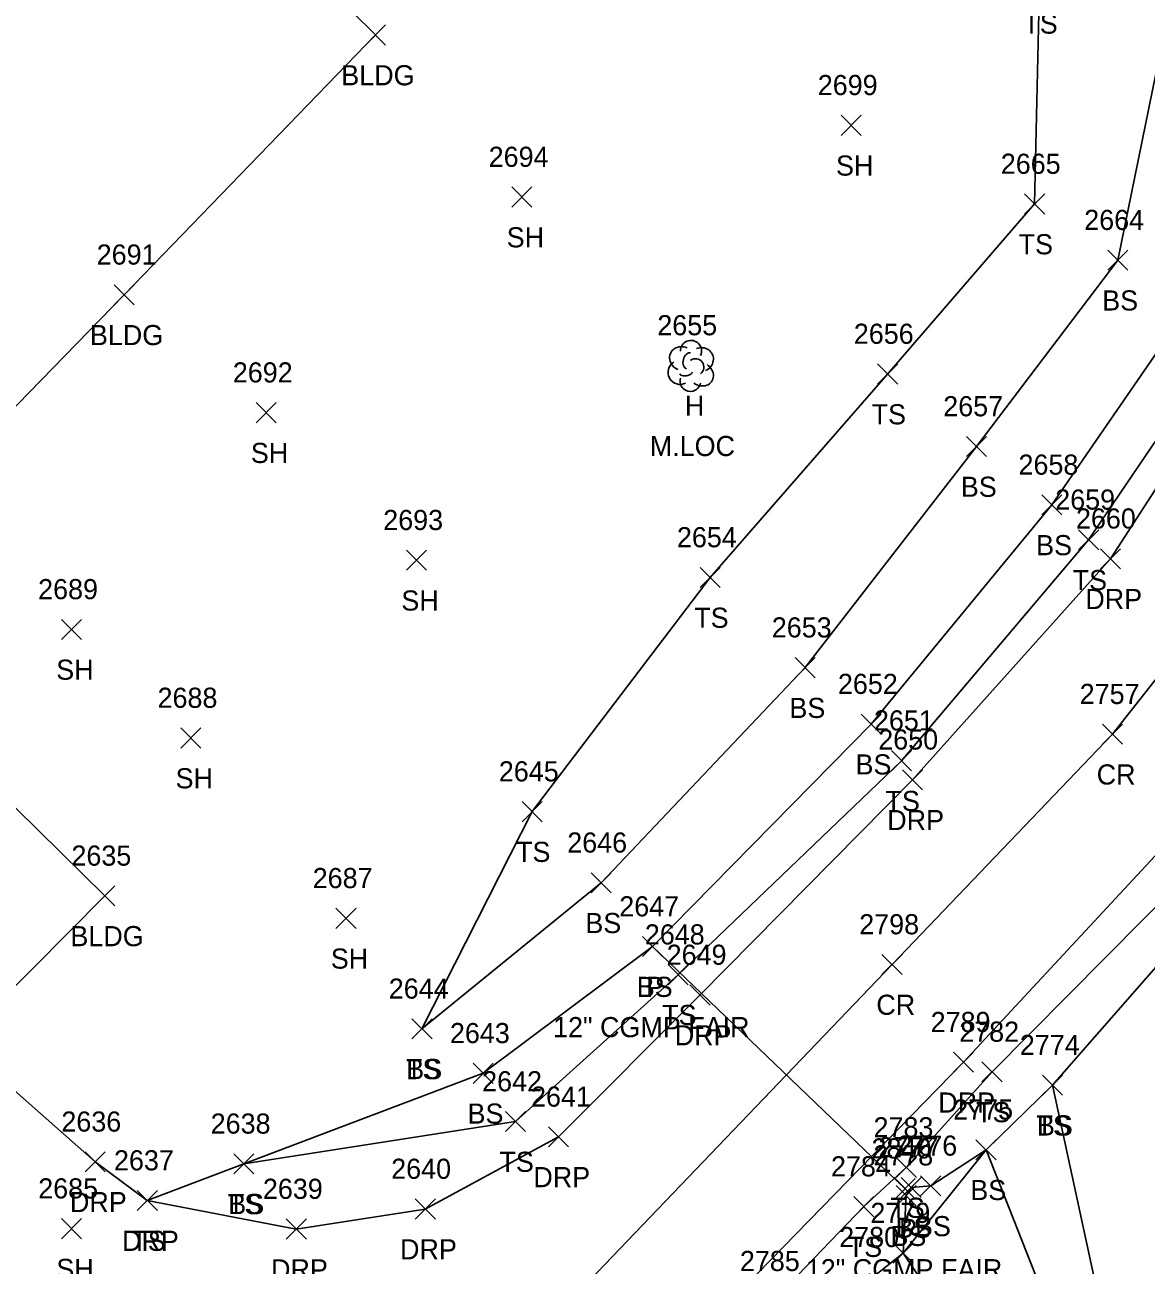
# Model space of a CAD drawing. Extents: x 1472233 to 1475777, y 540726 to 543442.
# Drawn here: x 1474005.9 to 1474117.3, y 542676.8 to 542800 of the extents above; entities that cross this region are included whole.
import ezdxf

# ---------------------------------------------------------------- set-up
doc = ezdxf.new("R2010")
doc.units = 0
for name, color, linetype in [('D_A', 7, 'Continuous'), ('D_C', 7, 'Continuous'), ('D_I', 7, 'Continuous'), ('D_TIC', 7, 'Continuous'), ('DCP', 7, 'Continuous'), ('L_A', 7, 'Continuous'), ('L_C', 7, 'Continuous'), ('L_I', 7, 'Continuous'), ('L_TIC', 7, 'Continuous'), ('LBC', 7, 'Continuous'), ('LELB', 7, 'Continuous'), ('LSOGP', 7, 'Continuous'), ('LTD', 7, 'Continuous'), ('P_A', 7, 'Continuous'), ('P_I', 7, 'Continuous'), ('P_TIC', 7, 'Continuous'), ('PRC', 7, 'Continuous'), ('R_A', 7, 'Continuous'), ('R_I', 7, 'Continuous'), ('R_TIC', 7, 'Continuous'), ('RDP', 7, 'Continuous')]:
    doc.layers.add(name, color=color, linetype=linetype)

msp = doc.modelspace()

# ---------------------------------------------------------------- linework, layer by layer
at = {"layer": 'D_TIC'}
for points in [[(1474067.24, 542707.41), (1474069.24, 542709.41)], [(1474069.24, 542707.41), (1474067.24, 542709.41)], [(1474092.36, 542683.36), (1474094.36, 542685.36)], [(1474094.36, 542683.36), (1474092.36, 542685.36)]]:
    msp.add_lwpolyline(points, dxfattribs=at)
at = {"layer": 'DCP'}
msp.add_lwpolyline([(1474068.24, 542708.41), (1474093.36, 542684.36)], dxfattribs=at)
at = {"layer": 'L_TIC'}
for points in [[(1474039.72, 542797.97), (1474041.72, 542799.97)], [(1474041.72, 542797.97), (1474039.72, 542799.97)], [(1474086.99, 542789), (1474088.99, 542791)], [(1474088.99, 542789), (1474086.99, 542791)], [(1474054.26, 542781.87), (1474056.26, 542783.87)], [(1474056.26, 542781.87), (1474054.26, 542783.87)], [(1474105.22, 542781.18), (1474107.22, 542783.18)], [(1474107.22, 542781.18), (1474105.22, 542783.18)], [(1474113.5, 542775.6), (1474115.5, 542777.6)], [(1474115.5, 542775.6), (1474113.5, 542777.6)], [(1474014.74, 542772.16), (1474016.74, 542774.16)], [(1474016.74, 542772.16), (1474014.74, 542774.16)], [(1474090.61, 542764.29), (1474092.61, 542766.29)], [(1474092.61, 542764.29), (1474090.61, 542766.29)], [(1474028.84, 542760.45), (1474030.84, 542762.45)], [(1474030.84, 542760.45), (1474028.84, 542762.45)], [(1474099.45, 542757.09), (1474101.45, 542759.09)], [(1474101.45, 542757.09), (1474099.45, 542759.09)], [(1474106.93, 542751.29), (1474108.93, 542753.29)], [(1474108.93, 542751.29), (1474106.93, 542753.29)], [(1474110.59, 542747.82), (1474112.59, 542749.82)], [(1474112.59, 542747.82), (1474110.59, 542749.82)], [(1474043.79, 542745.79), (1474045.79, 542747.79)], [(1474045.79, 542745.79), (1474043.79, 542747.79)], [(1474072.98, 542744.08), (1474074.98, 542746.08)], [(1474074.98, 542744.08), (1474072.98, 542746.08)], [(1474009.49, 542738.92), (1474011.49, 542740.92)], [(1474011.49, 542738.92), (1474009.49, 542740.92)], [(1474082.41, 542735.12), (1474084.41, 542737.12)], [(1474084.41, 542735.12), (1474082.41, 542737.12)], [(1474088.98, 542729.51), (1474090.98, 542731.51)], [(1474090.98, 542729.51), (1474088.98, 542731.51)], [(1474021.35, 542728.13), (1474023.35, 542730.13)], [(1474023.35, 542728.13), (1474021.35, 542730.13)], [(1474091.99, 542725.88), (1474093.99, 542727.88)], [(1474093.99, 542725.88), (1474091.99, 542727.88)], [(1474055.28, 542720.82), (1474057.28, 542722.82)], [(1474057.28, 542720.82), (1474055.28, 542722.82)], [(1474062.13, 542713.75), (1474064.13, 542715.75)], [(1474064.13, 542713.75), (1474062.13, 542715.75)], [(1474012.8, 542712.45), (1474014.8, 542714.45)], [(1474014.8, 542712.45), (1474012.8, 542714.45)], [(1474036.78, 542710.22), (1474038.78, 542712.22)], [(1474038.78, 542710.22), (1474036.78, 542712.22)], [(1474067.24, 542707.41), (1474069.24, 542709.41)], [(1474069.24, 542707.41), (1474067.24, 542709.41)], [(1474069.79, 542704.62), (1474071.79, 542706.62)], [(1474071.79, 542704.62), (1474069.79, 542706.62)], [(1474044.33, 542699.24), (1474046.33, 542701.24)], [(1474046.33, 542699.24), (1474044.33, 542701.24)], [(1474044.33, 542699.24), (1474046.33, 542701.24)], [(1474046.33, 542699.24), (1474044.33, 542701.24)], [(1474050.42, 542694.82), (1474052.42, 542696.82)], [(1474052.42, 542694.82), (1474050.42, 542696.82)], [(1474100.99, 542694.96), (1474102.99, 542696.96)], [(1474102.99, 542694.96), (1474100.99, 542696.96)], [(1474107, 542693.64), (1474109, 542695.64)], [(1474109, 542693.64), (1474107, 542695.64)], [(1474107, 542693.64), (1474109, 542695.64)], [(1474109, 542693.64), (1474107, 542695.64)], [(1474053.62, 542690.03), (1474055.62, 542692.03)], [(1474055.62, 542690.03), (1474053.62, 542692.03)], [(1474100.39, 542687.23), (1474102.39, 542689.23)], [(1474102.39, 542687.23), (1474100.39, 542689.23)], [(1474100.39, 542687.23), (1474102.39, 542689.23)], [(1474102.39, 542687.23), (1474100.39, 542689.23)], [(1474026.63, 542685.83), (1474028.63, 542687.83)], [(1474028.63, 542685.83), (1474026.63, 542687.83)], [(1474026.63, 542685.83), (1474028.63, 542687.83)], [(1474028.63, 542685.83), (1474026.63, 542687.83)], [(1474092.47, 542685.46), (1474094.47, 542687.46)], [(1474094.47, 542685.46), (1474092.47, 542687.46)], [(1474092.95, 542683.48), (1474094.95, 542685.48)], [(1474094.95, 542683.48), (1474092.95, 542685.48)], [(1474094.89, 542683.64), (1474096.89, 542685.64)], [(1474096.89, 542683.64), (1474094.89, 542685.64)], [(1474017.03, 542682.18), (1474019.03, 542684.18)], [(1474019.03, 542682.18), (1474017.03, 542684.18)], [(1474092.45, 542682.67), (1474094.45, 542684.67)], [(1474094.45, 542682.67), (1474092.45, 542684.67)], [(1474088.24, 542681.58), (1474090.24, 542683.58)], [(1474090.24, 542681.58), (1474088.24, 542683.58)], [(1474009.5, 542679.39), (1474011.5, 542681.39)], [(1474011.5, 542679.39), (1474009.5, 542681.39)], [(1474092.16, 542676.96), (1474094.16, 542678.96)], [(1474094.16, 542676.96), (1474092.16, 542678.96)], [(1474092.16, 542676.96), (1474094.16, 542678.96)], [(1474094.16, 542676.96), (1474092.16, 542678.96)]]:
    msp.add_lwpolyline(points, dxfattribs=at)
at = {"layer": 'LBC'}
msp.add_lwpolyline([(1473611.81, 542877.43), (1473647.84, 542842.15), (1473684.15, 542806.79), (1473712.79, 542779.19), (1473741.79, 542750.87), (1473773.96, 542719.66), (1473804, 542690.56), (1473836.45, 542659.06), (1473871.86, 542624.85), (1473901.94, 542656.08), (1473913.55, 542668.06), (1473934.21, 542647.92), (1473934.79, 542648.35), (1473977.15, 542693.11), (1473991.17, 542706.54), (1473991.24, 542706.56), (1473999.37, 542698.9), (1474013.8, 542713.45), (1473985.08, 542741.69), (1474015.74, 542773.16), (1474040.72, 542798.97), (1474028.75, 542810.8)], dxfattribs=at)
at = {"layer": 'LELB'}
for points in [[(1474018.03, 542683.18), (1474027.63, 542686.83), (1474054.62, 542691.03), (1474070.79, 542705.62), (1474092.99, 542726.88), (1474111.59, 542748.82), (1474125.85, 542769.85), (1474132.06, 542791.22), (1474131.8, 542814.84), (1474116.48, 542854.31), (1474111.7, 542860.51)], [(1474027.63, 542686.83), (1474051.42, 542695.82), (1474068.24, 542708.41), (1474089.98, 542730.51), (1474107.93, 542752.29), (1474121.88, 542772.53), (1474127.08, 542791.58), (1474127.12, 542813.94), (1474113.55, 542845.74), (1474102.69, 542855.23)], [(1474045.33, 542700.24), (1474063.13, 542714.75), (1474083.41, 542736.12), (1474100.45, 542758.09), (1474114.5, 542776.6), (1474118.95, 542798.51), (1474116.01, 542812.59), (1474102.38, 542835.59), (1474091.33, 542848.77)], [(1474045.33, 542700.24), (1474056.28, 542721.82), (1474073.98, 542745.08), (1474091.61, 542765.29), (1474106.22, 542782.18), (1474106.69, 542804.1), (1474107.48, 542810.21), (1474096.9, 542832.11), (1474081.02, 542842.42)], [(1474161.33, 542816.84), (1474161.97, 542792.29), (1474154.87, 542762.03), (1474144.32, 542744.44), (1474124.61, 542718.74), (1474101.99, 542695.96), (1474093.47, 542686.46), (1474089.24, 542682.58), (1474080.19, 542673.18), (1474075.15, 542661.11), (1474077.15, 542641.54), (1474095.47, 542632.72), (1474116.89, 542615.57), (1474111.23, 542585.69), (1474090.52, 542556.35), (1474073.67, 542551.32), (1474038.07, 542519.87), (1474011.53, 542544.93), (1473997.92, 542550.92)], [(1474168.42, 542758.16), (1474161.08, 542732.65), (1474152.4, 542685.62), (1474143.99, 542650.7), (1474139.21, 542638.25), (1474125.13, 542652.19), (1474113.17, 542670.76), (1474108, 542694.64)], [(1474147.6, 542740.17), (1474126.67, 542715.96), (1474108, 542694.64), (1474101.39, 542688.23), (1474093.16, 542677.96), (1474090.14, 542675.56), (1474083.3, 542668.09), (1474080.25, 542657.73), (1474086.54, 542649.05), (1474102.87, 542638.26), (1474116.97, 542621), (1474129.54, 542610.53)], [(1474165.95, 542731.94), (1474157.14, 542683.61), (1474148.57, 542649.89), (1474143.29, 542635.5), (1474139.19, 542631.93), (1474131.36, 542636.12), (1474120.53, 542648.69), (1474108.56, 542670.06), (1474101.39, 542688.23), (1474095.89, 542684.64), (1474093.95, 542684.48), (1474093.45, 542683.67), (1474093.16, 542677.96), (1474112.56, 542649.15), (1474130.63, 542628.83), (1474135.77, 542616.46), (1474134.45, 542606.68), (1474129.24, 542593.89), (1474099.76, 542548.63), (1474087.76, 542535.06), (1474054.57, 542501.68), (1474028.74, 542469.85), (1474011.69, 542457.24), (1473991.56, 542429.6)]]:
    msp.add_lwpolyline(points, dxfattribs=at)
at = {"layer": 'LSOGP'}
msp.add_lwpolyline([(1473684.15, 542806.79), (1473712.79, 542779.19), (1473741.79, 542750.87), (1473773.96, 542719.66), (1473804, 542690.56), (1473836.45, 542659.06), (1473871.86, 542624.85), (1473901.94, 542656.08), (1473913.55, 542668.06), (1473934.21, 542647.92), (1473934.79, 542648.35), (1473977.15, 542693.11), (1473991.17, 542706.54), (1473991.24, 542706.56), (1473999.37, 542698.9), (1474013.8, 542713.45), (1473985.08, 542741.69), (1474015.74, 542773.16), (1474040.72, 542798.97), (1474028.75, 542810.8)], dxfattribs=at)
at = {"layer": 'LTD'}
msp.add_line((1474072.02, 542766.14), (1474072.02, 542766.14), dxfattribs=at)
msp.add_line((1474072.02, 542766.14), (1474072.02, 542766.14), dxfattribs=at)
msp.add_arc((1474072.07, 542767.58), 1.05, 335.5272, 180.9563, dxfattribs=at)
for centre, major_axis, ratio, start_param, end_param in [((1474071.23, 542766.81), (1.21, -0.51), 0.895232, 1.570796, 4.712389), ((1474071.82, 542766.6), (-0.208, -0.792), 0.645439, 3.141593, 6.283185), ((1474073.07, 542766.73), (-1.14, -0.48), 0.949671, 1.570796, 4.712389), ((1474070.94, 542765.43), (0.58, -1.04), 0.959034, 3.141593, 6.283185), ((1474072.52, 542765.98), (-0.5, 0.667), 0.989748, 3.141593, 6.283185), ((1474073.02, 542765.31), (-1.09, 0.79), 0.841452, 1.570796, 4.712389), ((1474071.57, 542765.39), (-0.625, -0.083), 0.423636, 0, 3.141593), ((1474072.02, 542764.64), (0.26, 1.06), 0.942809, 1.570796, 4.712389)]:
    msp.add_ellipse(centre, major_axis=major_axis, ratio=ratio, start_param=start_param, end_param=end_param, dxfattribs=at)
at = {"layer": 'P_TIC'}
for points in [[(1474112.96, 542728.51), (1474114.96, 542730.51)], [(1474114.96, 542728.51), (1474112.96, 542730.51)], [(1474091.05, 542705.63), (1474093.05, 542707.63)], [(1474093.05, 542705.63), (1474091.05, 542707.63)]]:
    msp.add_lwpolyline(points, dxfattribs=at)
at = {"layer": 'PRC'}
msp.add_lwpolyline([(1474124.73, 542867.45), (1474138.24, 542842.57), (1474146.26, 542814.27), (1474147.99, 542793.2), (1474140.2, 542767.69), (1474131.39, 542751.59), (1474113.96, 542729.51), (1474092.05, 542706.63), (1474043.97, 542656.44), (1473995.22, 542610.58), (1473969.45, 542582.1), (1473923.18, 542533.15), (1473898.02, 542503.68), (1473870.62, 542473.58), (1473851.91, 542452.04)], dxfattribs=at)
at = {"layer": 'R_TIC'}
for points in [[(1474112.77, 542745.94), (1474114.77, 542747.94)], [(1474114.77, 542745.94), (1474112.77, 542747.94)], [(1474093.08, 542723.98), (1474095.08, 542725.98)], [(1474095.08, 542723.98), (1474093.08, 542725.98)], [(1474071.96, 542702.6), (1474073.96, 542704.6)], [(1474073.96, 542702.6), (1474071.96, 542704.6)], [(1474098.16, 542695.92), (1474100.16, 542697.92)], [(1474100.16, 542695.92), (1474098.16, 542697.92)], [(1474057.91, 542688.51), (1474059.91, 542690.51)], [(1474059.91, 542688.51), (1474057.91, 542690.51)], [(1474011.85, 542686.03), (1474013.85, 542688.03)], [(1474013.85, 542686.03), (1474011.85, 542688.03)], [(1474017.03, 542682.18), (1474019.03, 542684.18)], [(1474019.03, 542682.18), (1474017.03, 542684.18)], [(1474044.66, 542681.34), (1474046.66, 542683.34)], [(1474046.66, 542681.34), (1474044.66, 542683.34)], [(1474031.84, 542679.35), (1474033.84, 542681.35)], [(1474033.84, 542679.35), (1474031.84, 542681.35)]]:
    msp.add_lwpolyline(points, dxfattribs=at)
at = {"layer": 'RDP'}
for points in [[(1473999.37, 542698.9), (1474012.85, 542687.03), (1474018.03, 542683.18), (1474032.84, 542680.35), (1474045.66, 542682.34), (1474058.91, 542689.51), (1474072.96, 542703.6), (1474094.08, 542724.98), (1474113.77, 542746.94), (1474127.81, 542768.61), (1474135.07, 542788.71), (1474134.76, 542814.36), (1474118.74, 542856.08), (1474114.45, 542861.9)], [(1474156.9, 542816.07), (1474158.25, 542792.55), (1474149.71, 542763.53), (1474141.06, 542745.97), (1474122.05, 542721.57), (1474099.16, 542696.92), (1474072.3, 542669.38), (1474064.97, 542659.15), (1474064.16, 542645.99), (1474070.96, 542633.45), (1474104.89, 542594.5), (1474067.57, 542556.96), (1474038.11, 542526.02), (1474001.11, 542557.22), (1473988.17, 542557.88), (1473978.19, 542554.56), (1473968.9, 542548.06), (1473950.18, 542529.64), (1473913.19, 542491.65), (1473890.53, 542466.06), (1473881.45, 542451.89), (1473878.79, 542441.67), (1473879.57, 542429.36), (1473882.06, 542422.12)]]:
    msp.add_lwpolyline(points, dxfattribs=at)

# ---------------------------------------------------------------- texts
at = {"layer": 'D_A'}
for p in [(1474067.62, 542703.41), (1474092.74, 542679.36)]:
    msp.add_text('P', height=2, dxfattribs=at).set_placement(p)
at = {"layer": 'D_C'}
for p in [(1474058.36, 542699.41), (1474083.48, 542675.36)]:
    msp.add_text('12" CGMP FAIR', height=2, dxfattribs=at).set_placement(p)
at = {"layer": 'D_I'}
for s, p in [('2647', (1474064.94, 542711.41)), ('2840', (1474090.01, 542687.36))]:
    msp.add_text(s, height=2, dxfattribs=at).set_placement(p)
at = {"layer": 'L_A'}
for s, p in [('TS', (1474105.1, 542799.1)), ('BLDG', (1474037.31, 542793.97)), ('SH', (1474086.48, 542785)), ('SH', (1474053.75, 542777.87)), ('TS', (1474104.63, 542777.18)), ('BS', (1474112.94, 542771.6)), ('BLDG', (1474012.33, 542768.16)), ('H', (1474071.46, 542761.14)), ('TS', (1474090.02, 542760.29)), ('SH', (1474028.32, 542756.45)), ('BS', (1474098.89, 542753.09)), ('BS', (1474106.37, 542747.29)), ('TS', (1474110, 542743.82)), ('SH', (1474043.28, 542741.79)), ('TS', (1474072.39, 542740.08)), ('SH', (1474008.98, 542734.92)), ('BS', (1474081.85, 542731.12)), ('BS', (1474088.42, 542725.51)), ('SH', (1474020.84, 542724.13)), ('TS', (1474091.4, 542721.88)), ('TS', (1474054.68, 542716.82)), ('BS', (1474061.57, 542709.75)), ('BLDG', (1474010.39, 542708.45)), ('SH', (1474036.27, 542706.22)), ('BS', (1474066.68, 542703.41)), ('TS', (1474069.2, 542700.62)), ('TS', (1474043.74, 542695.24)), ('BS', (1474043.77, 542695.24)), ('BS', (1474049.86, 542690.82)), ('TS', (1474100.4, 542690.96)), ('TS', (1474106.41, 542689.64)), ('BS', (1474106.45, 542689.64)), ('TS', (1474053.03, 542686.03)), ('BS', (1474099.83, 542683.23)), ('BS', (1474099.83, 542683.23)), ('TS', (1474026.04, 542681.83)), ('BS', (1474026.08, 542681.83)), ('TS', (1474091.88, 542681.46)), ('BS', (1474092.39, 542679.48)), ('BS', (1474094.33, 542679.64)), ('TS', (1474016.44, 542678.18)), ('BS', (1474091.89, 542678.67)), ('TS', (1474087.65, 542677.58)), ('SH', (1474008.99, 542675.39))]:
    msp.add_text(s, height=2, dxfattribs=at).set_placement(p)
at = {"layer": 'L_C'}
msp.add_text('M.LOC', height=2, dxfattribs=at).set_placement((1474067.97, 542757.14))
at = {"layer": 'L_I'}
for s, p in [('2699', (1474084.67, 542793)), ('2694', (1474051.96, 542785.87)), ('2665', (1474102.86, 542785.18)), ('2664', (1474111.15, 542779.6)), ('2691', (1474013, 542776.16)), ('2655', (1474068.72, 542769.14)), ('2656', (1474088.25, 542768.29)), ('2692', (1474026.53, 542764.45)), ('2657', (1474097.14, 542761.09)), ('2658', (1474104.62, 542755.29)), ('2659', (1474108.27, 542751.82)), ('2693', (1474041.48, 542749.79)), ('2654', (1474070.67, 542748.08)), ('2689', (1474007.18, 542742.92)), ('2653', (1474080.1, 542739.12)), ('2652', (1474086.67, 542733.51)), ('2688', (1474019.05, 542732.13)), ('2651', (1474090.25, 542729.88)), ('2645', (1474052.97, 542724.82)), ('2646', (1474059.77, 542717.75)), ('2635', (1474010.49, 542716.45)), ('2687', (1474034.47, 542714.22)), ('2647', (1474064.94, 542711.41)), ('2648', (1474067.48, 542708.62)), ('2644', (1474042.03, 542703.24)), ('2644', (1474042.03, 542703.24)), ('2782', (1474098.73, 542698.96)), ('2643', (1474048.11, 542698.82)), ('2774', (1474104.75, 542697.64)), ('2774', (1474104.75, 542697.64)), ('2642', (1474051.31, 542694.03)), ('2775', (1474098.13, 542691.23)), ('2775', (1474098.13, 542691.23)), ('2638', (1474024.33, 542689.83)), ('2638', (1474024.33, 542689.83)), ('2783', (1474090.21, 542689.46)), ('2778', (1474090.19, 542686.67)), ('2777', (1474090.69, 542687.48)), ('2776', (1474092.58, 542687.64)), ('2637', (1474014.72, 542686.18)), ('2784', (1474085.98, 542685.58)), ('2685', (1474007.19, 542683.39)), ('2779', (1474089.9, 542680.96)), ('2779', (1474089.9, 542680.96)), ('2780', (1474086.8, 542678.56)), ('2780', (1474086.8, 542678.56)), ('2785', (1474076.93, 542676.18))]:
    msp.add_text(s, height=2, dxfattribs=at).set_placement(p)
at = {"layer": 'P_A'}
for p in [(1474112.39, 542724.51), (1474090.49, 542701.63)]:
    msp.add_text('CR', height=2, dxfattribs=at).set_placement(p)
at = {"layer": 'P_I'}
for s, p in [('2757', (1474110.7, 542732.51)), ('2798', (1474088.79, 542709.63))]:
    msp.add_text(s, height=2, dxfattribs=at).set_placement(p)
at = {"layer": 'R_A'}
for p in [(1474111.26, 542741.94), (1474091.57, 542719.98), (1474070.45, 542698.6), (1474096.64, 542691.92), (1474056.4, 542684.51), (1474010.34, 542682.03), (1474015.52, 542678.18), (1474043.15, 542677.34), (1474030.33, 542675.35)]:
    msp.add_text('DRP', height=2, dxfattribs=at).set_placement(p)
at = {"layer": 'R_I'}
for s, p in [('2660', (1474110.33, 542749.94)), ('2650', (1474090.68, 542727.98)), ('2649', (1474069.65, 542706.6)), ('2789', (1474095.89, 542699.92)), ('2641', (1474056.17, 542692.51)), ('2636', (1474009.49, 542690.03)), ('2637', (1474014.72, 542686.18)), ('2640', (1474042.27, 542685.34)), ('2639', (1474029.52, 542683.35))]:
    msp.add_text(s, height=2, dxfattribs=at).set_placement(p)

doc.saveas('drawing.dxf')
